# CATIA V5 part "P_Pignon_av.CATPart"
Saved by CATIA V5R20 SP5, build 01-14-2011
Part number: Pignon_av
Bounding box of the stored display mesh (mm): x -5 to 5, y 410 to 420, z 140 to 150
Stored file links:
  U:\2A\CFAO\dossier sans titre\P_Pignon_av.CATPart
  U:\2A\CFAO\dossier sans titre\Gouvernail.CATProduct
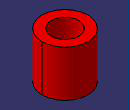
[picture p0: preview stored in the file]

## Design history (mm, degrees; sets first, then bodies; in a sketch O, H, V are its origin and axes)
Set1
  Point1: linked copy from another document
Body1 (main body)
  Sketch1 on xy-plane, origin (0, 0, 0), H (1, 0, 0), V (0, 1, 0)
    circle A1 centre (0, 415) radius 5
    point P1 (0, 415)
    reference projected point E1 (0, 415) from Point1
    radius A1 = 5
    coincidence: P1 E1
  Pad1: profile Sketch1, direction (0, 0, 1), length 150, opposite side length -140
  Sketch2 on end face of Pad1, origin (0, 415, 150), H (1, 0, 0), V (0, 1, 0)
    point P1 (0, 0)
  Hole1: placed by Sketch2, at (0, 415, 150) direction (0, 0, -1), diameter 6, through (limit type 3)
